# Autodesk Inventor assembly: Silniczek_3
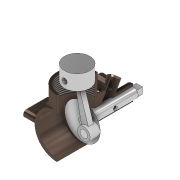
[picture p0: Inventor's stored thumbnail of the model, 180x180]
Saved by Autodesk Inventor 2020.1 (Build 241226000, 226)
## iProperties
Manager: www.cadconsulting.pl
Company: Fabian Stasiak CAD Consulting
Created: 2019-06
Part Number: Silniczek_3
Document SubType Name: Assembly
Designer: F.Stasiak
Author: F.Stasiak
Subject: Zbiór ćwiczeń. Autodesk Inventor 2020. Kurs podstawowy
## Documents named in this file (5)
- C:\2020_Kurs_podstawowy\R6 Zespoły\Wiązania\Silniczek\Silniczek_3.iam
- C:\2020_Kurs_podstawowy\R6 Zespoły\Wiązania\Silniczek\Korpus_234.ipt
- C:\2020_Kurs_podstawowy\R6 Zespoły\Wiązania\Silniczek\Wałek_234.ipt
- C:\2020_Kurs_podstawowy\R6 Zespoły\Wiązania\Silniczek\Tłok_234.ipt
- C:\2020_Kurs_podstawowy\R6 Zespoły\Wiązania\Silniczek\Korbowód_234.ipt
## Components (4 placed, 4 different names)
1. Korpus_234:1 — Wstawiające:1, Kątowe:1, Zestawiające:1
2. Wałek_234:1 — Wstawiające:1, Kątowe:1, Równoległe:1, Zestawiające:2
3. Tłok_234:1 — Zestawiające:1, Zestawiające:3
4. Korbowód_234:1 — Zestawiające:2, Zestawiające:3
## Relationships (6: Mate 3, Insert 1, Angle 1, Flush 1)
- Wstawiające:1 [Insert]: Korpus_234:1 ↔ Wałek_234:1
- Kątowe:1 [Angle]: Korpus_234:1 ↔ Wałek_234:1
- Zestawiające:1 [Mate]: Korpus_234:1 ↔ Tłok_234:1
- Równoległe:1 [Flush]: Wałek_234:1
- Zestawiające:2 [Mate]: Wałek_234:1 ↔ Korbowód_234:1
- Zestawiające:3 [Mate]: Tłok_234:1 ↔ Korbowód_234:1
